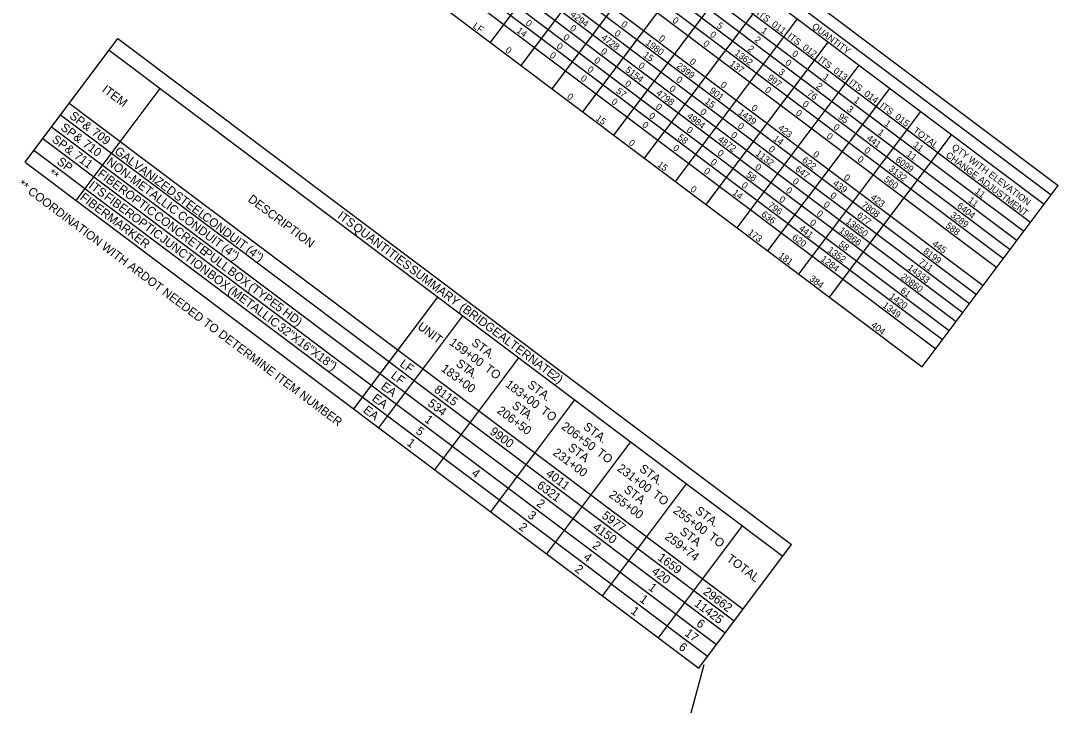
# Model space of a CAD drawing. Extents: x 626494 to 628870, y 365986 to 369334.
# Drawn here: x 627845.1 to 628284.5, y 368140 to 368433.2 of the extents above; entities that cross this region are included whole.
import ezdxf

# ---------------------------------------------------------------- set-up
doc = ezdxf.new("R2010")
doc.units = 0
for name, color, linetype in [('Default', 7, 'Continuous'), ('R_Grid_SCR50', 7, 'Continuous'), ('R_No Plot', 7, 'Continuous')]:
    doc.layers.add(name, color=color, linetype=linetype)

msp = doc.modelspace()

# ---------------------------------------------------------------- linework, layer by layer
at = {"layer": 'Default'}
for p, q in [((627992.22, 368582.9), (628284.46, 368363.46)), ((627989.23, 368578.92), (628281.47, 368359.47)), ((627980.5, 368567.29), (628272.74, 368347.85)), ((627977.63, 368563.47), (628269.87, 368344.03)), ((627974.76, 368559.65), (628267, 368340.2)), ((627971.89, 368555.83), (628264.13, 368336.38)), ((627969.02, 368552.01), (628261.26, 368332.56)), ((627966.15, 368548.18), (628258.39, 368328.74)), ((627960.41, 368540.54), (628252.65, 368321.09)), ((627957.54, 368536.72), (628249.78, 368317.27)), ((627954.67, 368532.89), (628246.91, 368313.45)), ((627951.8, 368529.07), (628244.04, 368309.63)), ((627948.93, 368525.25), (628241.17, 368305.8)), ((627946.05, 368521.43), (628238.3, 368301.98)), ((627940.31, 368513.78), (628232.56, 368294.34)), ((627943.18, 368517.61), (628235.43, 368298.16)), ((627934.57, 368506.14), (628226.82, 368286.69)), ((628043.99, 368423.98), (628098.64, 368496.76)), ((628095.65, 368492.78), (628278.48, 368355.49)), ((628057.04, 368414.18), (628108.71, 368482.98)), ((628070.1, 368404.37), (628121.77, 368473.17)), ((628083.16, 368394.56), (628134.83, 368463.36)), ((628096.22, 368384.76), (628147.89, 368453.56)), ((628109.28, 368374.95), (628160.94, 368443.75)), ((628122.34, 368365.14), (628174, 368433.94)), ((627846.95, 368373.34), (627886.27, 368425.7)), ((627886.27, 368425.7), (628171.56, 368211.47)), ((628135.4, 368355.34), (628187.06, 368424.14)), ((627882.52, 368420.71), (628167.81, 368206.48)), ((628148.46, 368345.53), (628200.12, 368414.33)), ((627868.56, 368357.11), (627904.13, 368404.48)), ((628161.52, 368335.72), (628213.18, 368404.52)), ((627865.67, 368398.27), (628150.96, 368184.04)), ((627861.93, 368393.28), (628147.21, 368179.06)), ((628174.58, 368325.92), (628226.24, 368394.72)), ((627858.18, 368388.3), (628143.47, 368174.07)), ((627854.44, 368383.31), (628139.73, 368169.08)), ((628187.64, 368316.11), (628239.3, 368384.91)), ((627850.69, 368378.32), (628135.98, 368164.1)), ((627846.95, 368373.34), (628132.24, 368159.11)), ((628226.82, 368286.69), (628284.46, 368363.46)), ((627986.16, 368268.8), (628021.74, 368316.17)), ((627996.76, 368260.84), (628032.33, 368308.21)), ((627996.76, 368260.84), (628032.33, 368308.21)), ((628020.45, 368243.05), (628056.02, 368290.43)), ((628044.14, 368225.27), (628079.71, 368272.64)), ((628067.82, 368207.48), (628103.4, 368254.85)), ((628091.51, 368189.69), (628127.08, 368237.07)), ((628115.2, 368171.9), (628150.77, 368219.28)), ((628115.2, 368171.9), (628150.77, 368219.28)), ((628132.24, 368159.11), (628171.56, 368211.47))]:
    msp.add_line(p, q, dxfattribs=at)
at = {"layer": 'R_No Plot'}
for p, q in [((627846.95, 368373.34), (627886.27, 368425.7)), ((627886.27, 368425.7), (627886.27, 368425.7)), ((627886.27, 368425.7), (628171.56, 368211.47)), ((627886.27, 368425.7), (627886.27, 368425.7)), ((627882.52, 368420.71), (628167.81, 368206.48)), ((627868.56, 368357.11), (627904.13, 368404.48)), ((627865.67, 368398.27), (628150.96, 368184.04)), ((627861.93, 368393.28), (628147.21, 368179.06)), ((627858.18, 368388.3), (628143.47, 368174.07)), ((627854.44, 368383.31), (628139.73, 368169.08)), ((627850.69, 368378.32), (628135.98, 368164.1)), ((627846.95, 368373.34), (628132.24, 368159.11)), ((627986.16, 368268.8), (628021.74, 368316.17)), ((627996.76, 368260.84), (628032.33, 368308.21)), ((627996.76, 368260.84), (628032.33, 368308.21)), ((628020.45, 368243.05), (628056.02, 368290.43)), ((628044.14, 368225.27), (628079.71, 368272.64)), ((628067.82, 368207.48), (628103.4, 368254.85)), ((628091.51, 368189.69), (628127.08, 368237.07)), ((628115.2, 368171.9), (628150.77, 368219.28)), ((628115.2, 368171.9), (628150.77, 368219.28)), ((628132.24, 368159.11), (628171.56, 368211.47)), ((628134.43, 368160.47), (628128.84, 368140))]:
    msp.add_line(p, q, dxfattribs=at)

# ---------------------------------------------------------------- texts
at = {"layer": 'Default'}
for s, height, p in [('4294', 2.809, (628077.6, 368435.31)), ('0', 2.81, (628120.77, 368432.78)), ('ITS_011', 2.809, (628156.48, 368435.85)), ('LF', 2.809, (628036.31, 368430.44)), ('0', 2.81, (628058.63, 368431.62)), ('0', 2.81, (628077.43, 368429.46)), ('0', 2.81, (628099.1, 368431.12)), ('5', 2.81, (628139.61, 368430.59)), ('QUANTITY', 2.809, (628179.9, 368430.22)), ('14', 2.809, (628054.85, 368428.48)), ('0', 2.81, (628074.56, 368425.64)), ('4728', 2.809, (628090.68, 368425.49)), ('0', 2.81, (628096.23, 368427.3)), ('0', 2.81, (628115.03, 368425.14)), ('0', 2.81, (628136.7, 368426.8)), ('2', 2.81, (628155.53, 368424.61)), ('1', 2.81, (628158.4, 368428.43)), ('ITS_012', 2.809, (628169.54, 368426.05)), ('0', 2.81, (628050.02, 368420.15)), ('0', 2.81, (628071.69, 368421.82)), ('0', 2.81, (628090.49, 368419.65)), ('1980', 2.809, (628109.47, 368423.33)), ('0', 2.81, (628133.83, 368422.97)), ('2', 2.81, (628152.66, 368420.78)), ('0', 2.81, (628068.82, 368417.99)), ('0', 2.81, (628087.62, 368415.83)), ('15', 2.809, (628108.43, 368418.13)), ('0', 2.81, (628128.09, 368415.33)), ('1362', 2.809, (628147.1, 368418.98)), ('0', 2.81, (628171.43, 368418.65)), ('ITS_013', 2.809, (628182.61, 368416.23)), ('0', 2.81, (628084.75, 368412.01)), ('5154', 2.809, (628100.85, 368411.87)), ('0', 2.81, (628106.42, 368413.67)), ('2399', 2.809, (628122.56, 368413.5)), ('137', 2.809, (628145.11, 368414.5)), ('3', 2.81, (628165.73, 368410.97)), ('0', 2.81, (628168.55, 368414.83)), ('0', 2.81, (628081.88, 368408.19)), ('0', 2.81, (628122.35, 368407.68)), ('997', 2.809, (628161.04, 368408.51)), ('1', 2.81, (628184.52, 368408.82)), ('ITS_014', 2.809, (628195.61, 368406.47)), ('ITEM', 3.664, (627879.19, 368403.38)), ('57', 2.809, (628096.93, 368402.86)), ('0', 2.81, (628100.68, 368406.02)), ('0', 2.81, (628119.48, 368403.86)), ('901', 2.809, (628136.52, 368403.02)), ('0', 2.81, (628141.14, 368405.52)), ('0', 2.81, (628159.94, 368403.36)), ('76', 2.809, (628177.86, 368401.87)), ('2', 2.81, (628181.65, 368404.99)), ('0', 2.81, (628076.14, 368400.54)), ('0', 2.81, (628094.94, 368398.38)), ('4798', 2.809, (628113.93, 368402.05)), ('15', 2.809, (628134.55, 368398.52)), ('1', 2.81, (628197.58, 368399.01)), ('0', 2.81, (628113.73, 368396.22)), ('0', 2.81, (628132.53, 368394.06)), ('1439', 2.809, (628148.67, 368393.89)), ('0', 2.81, (628154.2, 368395.72)), ('0', 2.81, (628173, 368393.55)), ('0', 2.81, (628175.87, 368397.38)), ('3', 2.81, (628194.72, 368395.18)), ('ITS_015', 2.809, (628208.72, 368396.62)), ('SP', 3.664, (627865.44, 368392.25)), ('15', 2.809, (628088.34, 368391.38)), ('0', 2.81, (628110.86, 368392.4)), ('4984', 2.809, (628126.97, 368392.26)), ('95', 2.809, (628190.95, 368392.03)), ('1', 2.81, (628210.64, 368389.21)), ('SP', 3.664, (627861.66, 368387.29)), (' &', 3.664, (627869.74, 368389.02)), (' 709', 3.664, (627873.74, 368386.02)), ('0', 2.81, (628107.99, 368388.57)), ('0', 2.81, (628126.79, 368386.41)), ('0', 2.81, (628148.46, 368388.07)), ('423', 2.809, (628165.52, 368387.22)), ('0', 2.81, (628188.93, 368387.57)), ('1', 2.81, (628207.77, 368385.38)), ('TOTAL', 2.809, (628222.72, 368386.11)), ('SP', 3.664, (627857.96, 368382.27)), (' &', 3.664, (627865.96, 368384.06)), (' 710', 3.664, (627869.96, 368381.06)), ('0', 2.81, (628102.25, 368380.93)), ('58', 2.809, (628123.04, 368383.25)), ('4872', 2.809, (628140.07, 368382.42)), ('0', 2.81, (628145.59, 368384.25)), ('14', 2.809, (628163.49, 368382.77)), ('0', 2.81, (628186.06, 368383.75)), ('441', 2.809, (628203.1, 368382.91)), (' &', 3.664, (627862.26, 368379.04)), (' 711', 3.664, (627866.26, 368376.04)), ('GALVANIZED', 3.664, (627884.5, 368377.25)), ('0', 2.81, (628121.05, 368378.77)), ('0', 2.81, (628139.85, 368376.61)), ('1132', 2.809, (628156, 368376.44)), ('0', 2.81, (628161.52, 368378.27)), ('0', 2.81, (628180.32, 368376.1)), ('0', 2.81, (628201.99, 368377.76)), ('11', 2.809, (628219.93, 368376.25)), ('11', 2.809, (628222.8, 368380.07)), ('QTY WITH ELEVATION', 2.8087, (628239.11, 368379.07)), ('SP', 3.664, (627860.12, 368372.85)), ('NON-METALLIC', 3.6645, (627881.08, 368372.71)), ('15', 2.809, (628114.46, 368371.76)), ('0', 2.81, (628136.98, 368372.78)), ('622', 2.809, (628175.7, 368373.6)), ('0', 2.81, (628199.12, 368373.94)), ('6099', 2.809, (628215.26, 368373.78)), ('CHANGE ADJUSTMENT', 2.8087, (628236.58, 368375.7)), ('**', 3.664, (627856.41, 368367.84)), ('FIBER', 3.664, (627877.34, 368367.72)), ('0', 2.81, (628134.11, 368368.96)), ('58', 2.809, (628152.03, 368367.46)), ('0', 2.81, (628155.78, 368370.62)), ('647', 2.809, (628172.81, 368369.79)), ('3132', 2.809, (628212.4, 368369.95)), ('ITS', 3.664, (627873.59, 368362.73)), ('0', 2.81, (628150.04, 368362.98)), ('0', 2.81, (628171.71, 368364.64)), ('439', 2.809, (628188.75, 368363.8)), ('0', 2.81, (628193.38, 368366.3)), ('560', 2.809, (628210.39, 368365.48)), ('FIBER', 3.664, (627869.85, 368357.75)), (' FIBER', 3.664, (627878.96, 368358.7)), (' OPTIC', 3.664, (627887.72, 368359.92)), (' STEEL', 3.664, (627908.5, 368359.22)), ('0', 2.81, (628128.37, 368361.32)), ('14', 2.809, (628146.27, 368359.84)), ('0', 2.81, (628168.84, 368360.82)), ('0', 2.81, (628187.64, 368358.65)), ('11', 2.809, (628248.92, 368360.46)), ('DESCRIPTION', 3.6645, (627941.01, 368356.95)), ('796', 2.809, (628161.32, 368354.51)), ('0', 2.81, (628165.97, 368356.99)), ('0', 2.81, (628184.77, 368354.83)), ('7808', 2.809, (628200.89, 368354.68)), ('423', 2.809, (628204.7, 368357.8)), ('6404', 2.809, (628241.34, 368354.19)), ('11', 2.809, (628246.05, 368356.64)), (' MARKER', 3.664, (627880.23, 368349.95)), (' OPTIC', 3.664, (627890.39, 368350.12)), (' CONCRETE', 3.664, (627899.96, 368350.73)), (' CONDUIT', 3.664, (627910.02, 368350.98)), (' CONDUIT', 3.664, (627920.33, 368350.35)), ('ITS', 3.664, (627978.94, 368349.92)), ('636', 2.809, (628158.45, 368350.69)), ('0', 2.81, (628181.9, 368351.01)), ('677', 2.809, (628198.93, 368350.18)), ('3289', 2.809, (628238.51, 368350.34)), (' QUANTITIES', 3.6645, (627984.31, 368345.89)), ('0', 2.81, (628179.03, 368347.19)), ('13650', 2.809, (628194.25, 368347.72)), ('588', 2.809, (628236.52, 368345.86)), (' JUNCTION', 3.664, (627902.62, 368340.93)), ('173', 2.809, (628152.75, 368343.02)), ('620', 2.809, (628171.5, 368340.89)), ('441', 2.809, (628174.4, 368344.68)), ('19866', 2.809, (628191.38, 368343.89)), (' (4")', 3.664, (627928.74, 368336.92)), ('58', 2.809, (628191.21, 368338.04)), ('445', 2.809, (628230.81, 368338.19)), (' PULL', 3.664, (627920.98, 368334.95)), (' (4")', 3.664, (627939.05, 368336.29)), ('181', 2.809, (628165.79, 368333.22)), ('1352', 2.809, (628186.57, 368335.55)), ('8199', 2.809, (628227.03, 368335.05)), (' SUMMARY', 3.664, (628008.11, 368328.01)), ('1284', 2.809, (628183.65, 368331.76)), ('14333', 2.809, (628220.41, 368328.07)), ('711', 2.809, (628225.06, 368330.55)), (' BOX', 3.664, (627922.61, 368325.93)), (' BOX', 3.664, (627931.22, 368327.26)), ('384', 2.809, (628178.81, 368323.45)), ('20860', 2.809, (628217.49, 368324.28)), (' (METALLIC', 3.664, (627931.51, 368319.25)), (' (TYPE', 3.664, (627940.12, 368320.58)), ('1420', 2.809, (628212.65, 368315.96)), ('61', 2.809, (628217.35, 368318.41)), (' 5', 3.664, (627951.46, 368312.06)), (' HD)', 3.664, (627954.57, 368309.73)), (' (BRIDGE', 3.664, (628029.49, 368311.96)), ('1349', 2.809, (628209.81, 368312.12)), (' 32"X16"X18")', 3.6645, (627952.45, 368303.52)), ('UNIT', 3.664, (628012.85, 368303.01)), ('404', 2.809, (628204.93, 368303.83)), ('159+00', 3.664, (628026.32, 368296.33)), ('STA.', 3.664, (628035.67, 368296.18)), (' ALTERNATE', 3.664, (628045.88, 368299.65)), ('LF', 3.664, (628005.28, 368287.24)), ('ST', 3.664, (628029.09, 368287.38)), ('183+00', 3.664, (628022.79, 368285.24)), ('A.', 3.664, (628033.42, 368284.12)), (' TO', 3.664, (628040.16, 368285.94)), ('LF', 3.664, (628001.54, 368282.26)), (' 2)', 3.664, (628068.46, 368282.7)), ('EA', 3.664, (627997.3, 368277.64)), ('8115', 3.664, (628019.81, 368276.33)), ('183+00', 3.664, (628050.01, 368278.54)), ('STA.', 3.664, (628059.36, 368278.4)), ('EA', 3.664, (627993.56, 368272.65)), ('534', 3.664, (628017.17, 368270.52)), ('EA', 3.664, (627989.81, 368267.67)), ('206+50', 3.664, (628046.47, 368267.45)), ('ST', 3.664, (628052.77, 368269.59)), ('A.', 3.664, (628057.11, 368266.34)), (' TO', 3.664, (628063.85, 368268.15)), ('1', 3.66, (628015.82, 368263.73)), ('5', 3.66, (628012.09, 368258.74)), ('9900', 3.664, (628043.44, 368258.59)), ('206+50', 3.664, (628073.7, 368260.75)), ('STA.', 3.664, (628083.04, 368260.61)), ('1', 3.66, (628008.33, 368253.76)), ('231+00', 3.664, (628070.16, 368249.66)), ('STA', 3.664, (628076.48, 368251.79)), (' TO', 3.664, (628087.53, 368250.36)), ('.', 3.66, (628083.45, 368246.56)), ('4', 3.66, (628035.71, 368241)), ('4011', 3.664, (628067.18, 368240.77)), ('231+00', 3.664, (628097.39, 368242.97)), ('STA.', 3.664, (628106.73, 368242.82)), ('6321', 3.664, (628063.43, 368235.78)), ('255+00', 3.664, (628093.85, 368231.87)), ('STA', 3.664, (628100.17, 368234)), (' TO', 3.664, (628111.22, 368232.58)), ('2', 3.66, (628063.2, 368228.16)), ('.', 3.66, (628107.13, 368228.77)), ('3', 3.66, (628059.47, 368223.16)), ('5977', 3.664, (628090.85, 368222.99)), ('255+00', 3.664, (628121.07, 368225.18)), ('STA.', 3.664, (628130.42, 368225.03)), ('2', 3.66, (628055.71, 368218.18)), ('4150', 3.664, (628087.08, 368218.03)), ('259+74', 3.664, (628117.52, 368214.1)), ('STA', 3.664, (628123.86, 368216.21)), (' TO', 3.664, (628134.91, 368214.79)), ('2', 3.66, (628086.89, 368210.37)), ('.', 3.66, (628130.82, 368210.98)), ('4', 3.66, (628083.08, 368205.43)), ('1659', 3.664, (628114.54, 368205.2)), ('TOTAL', 3.664, (628143.7, 368204.75)), ('2', 3.66, (628079.4, 368200.39)), ('420', 3.664, (628111.93, 368199.36)), ('1', 3.66, (628110.57, 368192.58)), ('29662', 3.664, (628133.75, 368190.78)), ('1', 3.66, (628106.83, 368187.6)), ('1', 3.66, (628103.08, 368182.61)), ('11425', 3.664, (628130.01, 368185.78)), ('6', 3.66, (628130.9, 368177.32)), ('17', 3.664, (628126, 368173.2)), ('6', 3.66, (628123.41, 368167.34))]:
    msp.add_text(s, height=height, rotation=323.0968, dxfattribs=at).set_placement(p)
at = {"layer": 'R_Grid_SCR50'}
msp.add_text('** COORDINATION WITH ARDOT NEEDED TO DETERMINE ITEM NUMBER', height=3.63, rotation=323.0968, dxfattribs=at).set_placement((627843.68, 368363.32))
at = {"layer": 'R_No Plot'}
for s, height, p in [('ITEM', 3.664, (627879.19, 368403.38)), ('SP', 3.664, (627865.44, 368392.25)), ('SP', 3.664, (627861.66, 368387.29)), (' &', 3.664, (627869.74, 368389.02)), (' 709', 3.664, (627873.74, 368386.02)), ('SP', 3.664, (627857.96, 368382.27)), (' &', 3.664, (627865.96, 368384.06)), (' 710', 3.664, (627869.96, 368381.06)), (' &', 3.664, (627862.26, 368379.04)), (' 711', 3.664, (627866.26, 368376.04)), ('GALVANIZED', 3.664, (627884.5, 368377.25)), ('SP', 3.664, (627860.12, 368372.85)), ('NON-METALLIC', 3.6645, (627881.08, 368372.71)), ('**', 3.664, (627856.41, 368367.84)), ('FIBER', 3.664, (627877.34, 368367.72)), ('ITS', 3.664, (627873.59, 368362.73)), ('FIBER', 3.664, (627869.85, 368357.75)), (' FIBER', 3.664, (627878.96, 368358.7)), (' OPTIC', 3.664, (627887.72, 368359.92)), (' STEEL', 3.664, (627908.5, 368359.22)), ('DESCRIPTION', 3.6645, (627941.01, 368356.95)), (' MARKER', 3.664, (627880.23, 368349.95)), (' OPTIC', 3.664, (627890.39, 368350.12)), (' CONCRETE', 3.664, (627899.96, 368350.73)), (' CONDUIT', 3.664, (627910.02, 368350.98)), (' CONDUIT', 3.664, (627920.33, 368350.35)), ('ITS', 3.664, (627978.94, 368349.92)), (' QUANTITIES', 3.6645, (627984.31, 368345.89)), (' JUNCTION', 3.664, (627902.62, 368340.93)), (' (4")', 3.664, (627928.74, 368336.92)), (' PULL', 3.664, (627920.98, 368334.95)), (' (4")', 3.664, (627939.05, 368336.29)), (' SUMMARY', 3.664, (628008.11, 368328.01)), (' BOX', 3.664, (627922.61, 368325.93)), (' BOX', 3.664, (627931.22, 368327.26)), (' (METALLIC', 3.664, (627931.51, 368319.25)), (' (TYPE', 3.664, (627940.12, 368320.58)), (' 5', 3.664, (627951.46, 368312.06)), (' HD)', 3.664, (627954.57, 368309.73)), (' (BRIDGE', 3.664, (628029.49, 368311.96)), (' 32"X16"X18")', 3.6645, (627952.45, 368303.52)), ('UNIT', 3.664, (628012.85, 368303.01)), ('159+00', 3.664, (628026.32, 368296.33)), ('STA.', 3.664, (628035.67, 368296.18)), (' ALTERNATE', 3.664, (628045.88, 368299.65)), ('LF', 3.664, (628005.28, 368287.24)), ('ST', 3.664, (628029.09, 368287.38)), ('183+00', 3.664, (628022.79, 368285.24)), ('A.', 3.664, (628033.42, 368284.12)), (' TO', 3.664, (628040.16, 368285.94)), ('LF', 3.664, (628001.54, 368282.26)), (' 2)', 3.664, (628068.46, 368282.7)), ('EA', 3.664, (627997.3, 368277.64)), ('8115', 3.664, (628019.81, 368276.33)), ('183+00', 3.664, (628050.01, 368278.54)), ('STA.', 3.664, (628059.36, 368278.4)), ('EA', 3.664, (627993.56, 368272.65)), ('534', 3.664, (628017.17, 368270.52)), ('EA', 3.664, (627989.81, 368267.67)), ('206+50', 3.664, (628046.47, 368267.45)), ('ST', 3.664, (628052.77, 368269.59)), ('A.', 3.664, (628057.11, 368266.34)), (' TO', 3.664, (628063.85, 368268.15)), ('1', 3.66, (628015.82, 368263.73)), ('5', 3.66, (628012.09, 368258.74)), ('9900', 3.664, (628043.44, 368258.59)), ('206+50', 3.664, (628073.7, 368260.75)), ('STA.', 3.664, (628083.04, 368260.61)), ('1', 3.66, (628008.33, 368253.76)), ('231+00', 3.664, (628070.16, 368249.66)), ('STA', 3.664, (628076.48, 368251.79)), (' TO', 3.664, (628087.53, 368250.36)), ('.', 3.66, (628083.45, 368246.56)), ('4', 3.66, (628035.71, 368241)), ('4011', 3.664, (628067.18, 368240.77)), ('231+00', 3.664, (628097.39, 368242.97)), ('STA.', 3.664, (628106.73, 368242.82)), ('6321', 3.664, (628063.43, 368235.78)), ('255+00', 3.664, (628093.85, 368231.87)), ('STA', 3.664, (628100.17, 368234)), (' TO', 3.664, (628111.22, 368232.58)), ('2', 3.66, (628063.2, 368228.16)), ('.', 3.66, (628107.13, 368228.77)), ('3', 3.66, (628059.47, 368223.16)), ('5977', 3.664, (628090.85, 368222.99)), ('255+00', 3.664, (628121.07, 368225.18)), ('STA.', 3.664, (628130.42, 368225.03)), ('2', 3.66, (628055.71, 368218.18)), ('4150', 3.664, (628087.08, 368218.03)), ('259+74', 3.664, (628117.52, 368214.1)), ('STA', 3.664, (628123.86, 368216.21)), (' TO', 3.664, (628134.91, 368214.79)), ('2', 3.66, (628086.89, 368210.37)), ('.', 3.66, (628130.82, 368210.98)), ('4', 3.66, (628083.08, 368205.43)), ('1659', 3.664, (628114.54, 368205.2)), ('TOTAL', 3.664, (628143.7, 368204.75)), ('2', 3.66, (628079.4, 368200.39)), ('420', 3.664, (628111.93, 368199.36)), ('1', 3.66, (628110.57, 368192.58)), ('29662', 3.664, (628133.75, 368190.78)), ('1', 3.66, (628106.83, 368187.6)), ('1', 3.66, (628103.08, 368182.61)), ('11425', 3.664, (628130.01, 368185.78)), ('6', 3.66, (628130.9, 368177.32)), ('17', 3.664, (628126, 368173.2)), ('6', 3.66, (628123.41, 368167.34))]:
    msp.add_text(s, height=height, rotation=323.0968, dxfattribs=at).set_placement(p)

doc.saveas('drawing.dxf')
